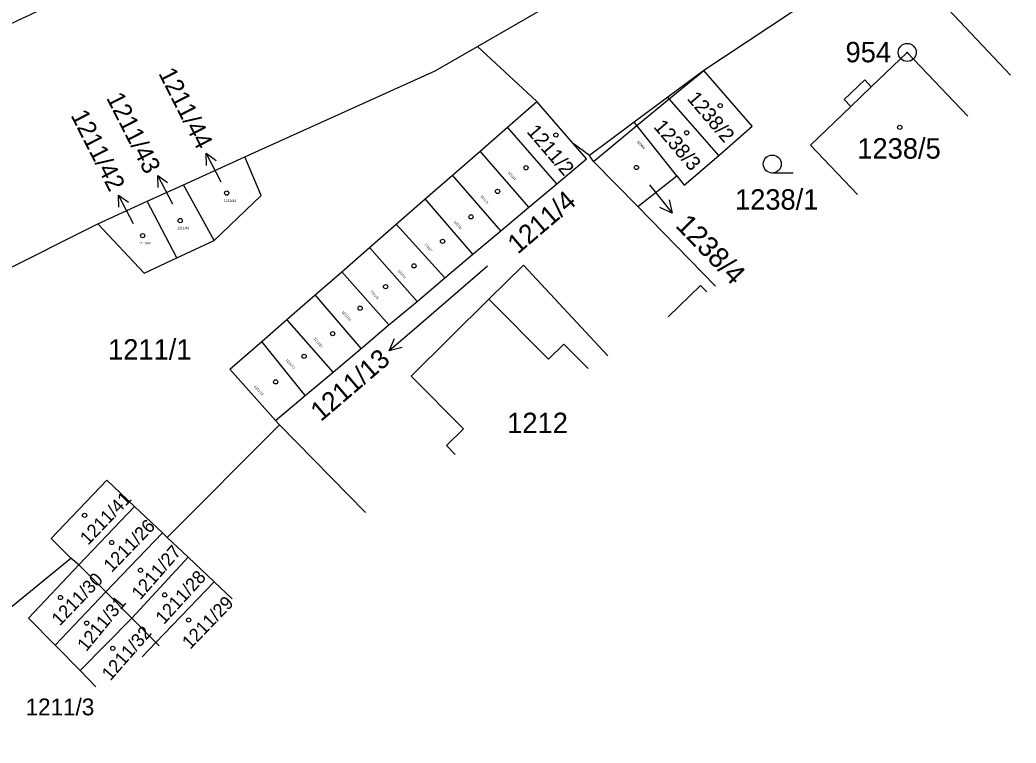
# Model space of a CAD drawing. Extents: x -825057 to -819383, y -1071633 to -1067888.
# Drawn here: x -820150.4 to -820067.4, y -1069566.8 to -1069506.6 of the extents above; entities that cross this region are included whole.
import ezdxf

# ---------------------------------------------------------------- set-up
doc = ezdxf.new("R2010")
doc.units = 0
for name, color, linetype in [('Vrstva 1', 7, 'Continuous'), ('Vrstva 10', 7, 'Continuous'), ('Vrstva 16', 7, 'Continuous'), ('Vrstva 17', 7, 'Continuous'), ('Vrstva 18', 7, 'Continuous'), ('Vrstva 19', 7, 'Continuous'), ('Vrstva 24', 7, 'Continuous'), ('Vrstva 25', 7, 'Continuous'), ('Vrstva 4', 7, 'Continuous')]:
    doc.layers.add(name, color=color, linetype=linetype)

msp = doc.modelspace()

# ---------------------------------------------------------------- linework, layer by layer
at = {"layer": 'Vrstva 1'}
for p, q in [((-820112.25, -1069508.76), (-820085.07, -1069493.07)), ((-820077.91, -1069500.52), (-820093.39, -1069510.76)), ((-820077.91, -1069500.52), (-820067.83, -1069511.15)), ((-820115.78, -1069510.8), (-820112.25, -1069508.76)), ((-820107.3, -1069513.36), (-820112.25, -1069508.76)), ((-820076.45, -1069509.27), (-820079.44, -1069512.13)), ((-820071.39, -1069514.58), (-820076.45, -1069509.27)), ((-820131.65, -1069517.97), (-820115.78, -1069510.8)), ((-820093.39, -1069510.76), (-820096.39, -1069512.99)), ((-820089.36, -1069515.42), (-820093.39, -1069510.76)), ((-820079.99, -1069511.56), (-820081.69, -1069513.18)), ((-820079.44, -1069512.13), (-820079.99, -1069511.56)), ((-820109.74, -1069515.49), (-820107.3, -1069513.36)), ((-820104.28, -1069516.84), (-820107.3, -1069513.36)), ((-820096.39, -1069512.99), (-820099.19, -1069515.08)), ((-820096.27, -1069513.13), (-820096.39, -1069512.99)), ((-820092.15, -1069517.84), (-820096.27, -1069513.13)), ((-820081.69, -1069513.18), (-820081.14, -1069513.76)), ((-820081.14, -1069513.76), (-820084.51, -1069516.99)), ((-820099.19, -1069515.08), (-820102.92, -1069517.86)), ((-820098.97, -1069515.36), (-820099.19, -1069515.08)), ((-820112.04, -1069517.49), (-820109.74, -1069515.49)), ((-820105.64, -1069520.2), (-820109.74, -1069515.49)), ((-820095.65, -1069519.53), (-820098.97, -1069515.36)), ((-820092.15, -1069517.84), (-820089.36, -1069515.42)), ((-820114.34, -1069519.49), (-820112.04, -1069517.49)), ((-820107.97, -1069522.16), (-820112.04, -1069517.49)), ((-820102.92, -1069517.86), (-820104.28, -1069516.84)), ((-820103.16, -1069518.12), (-820104.28, -1069516.84)), ((-820084.51, -1069516.99), (-820080.58, -1069521.09)), ((-820136.74, -1069520.29), (-820131.65, -1069517.97)), ((-820130.28, -1069521.17), (-820131.65, -1069517.97)), ((-820105.64, -1069520.2), (-820103.16, -1069518.12)), ((-820102.59, -1069518.34), (-820102.92, -1069517.86)), ((-820098.9, -1069522.11), (-820102.59, -1069518.34)), ((-820095.02, -1069520.33), (-820092.15, -1069517.84)), ((-820116.6, -1069521.46), (-820114.34, -1069519.49)), ((-820110.3, -1069524.12), (-820114.34, -1069519.49)), ((-820098.9, -1069522.11), (-820095.65, -1069519.53)), ((-820095.65, -1069519.53), (-820095.02, -1069520.33)), ((-820139.77, -1069521.66), (-820136.74, -1069520.29)), ((-820134.2, -1069524.92), (-820136.74, -1069520.29)), ((-820107.97, -1069522.16), (-820105.64, -1069520.2)), ((-820143.89, -1069523.54), (-820139.77, -1069521.66)), ((-820137.31, -1069526.37), (-820139.77, -1069521.66)), ((-820134.2, -1069524.92), (-820130.28, -1069521.17)), ((-820119.02, -1069523.57), (-820116.6, -1069521.46)), ((-820112.63, -1069526.08), (-820116.6, -1069521.46)), ((-820110.3, -1069524.12), (-820107.97, -1069522.16)), ((-820092.42, -1069528.74), (-820098.9, -1069522.11)), ((-820153.6, -1069528.41), (-820143.89, -1069523.54)), ((-820143.89, -1069523.54), (-820140.03, -1069527.64)), ((-820121.24, -1069525.51), (-820119.02, -1069523.57)), ((-820114.96, -1069528.04), (-820119.02, -1069523.57)), ((-820112.63, -1069526.08), (-820110.3, -1069524.12)), ((-820137.31, -1069526.37), (-820134.2, -1069524.92)), ((-820123.56, -1069527.53), (-820121.24, -1069525.51)), ((-820117.29, -1069530), (-820121.24, -1069525.51)), ((-820140.03, -1069527.64), (-820137.31, -1069526.37)), ((-820114.96, -1069528.04), (-820112.63, -1069526.08)), ((-820125.78, -1069529.46), (-820123.56, -1069527.53)), ((-820119.63, -1069531.96), (-820123.56, -1069527.53)), ((-820108.42, -1069526.98), (-820111.3, -1069529.82)), ((-820101.4, -1069534.54), (-820108.42, -1069526.98)), ((-820117.29, -1069530), (-820114.96, -1069528.04)), ((-820128.14, -1069531.52), (-820125.78, -1069529.46)), ((-820121.95, -1069533.92), (-820125.78, -1069529.46)), ((-820119.63, -1069531.96), (-820117.29, -1069530)), ((-820111.3, -1069529.82), (-820117.77, -1069536.24)), ((-820130.22, -1069533.33), (-820128.14, -1069531.52)), ((-820124.29, -1069535.88), (-820128.14, -1069531.52)), ((-820121.95, -1069533.92), (-820119.63, -1069531.96)), ((-820132.89, -1069535.65), (-820130.22, -1069533.33)), ((-820126.62, -1069537.84), (-820130.22, -1069533.33)), ((-820124.29, -1069535.88), (-820121.95, -1069533.92)), ((-820129.09, -1069539.92), (-820132.89, -1069535.65)), ((-820126.62, -1069537.84), (-820124.29, -1069535.88)), ((-820117.77, -1069536.24), (-820113.42, -1069540.6)), ((-820129.09, -1069539.92), (-820126.62, -1069537.84)), ((-820128.76, -1069540.28), (-820129.09, -1069539.92)), ((-820128.76, -1069540.28), (-820138.1, -1069549.65)), ((-820121.59, -1069547.59), (-820128.76, -1069540.28)), ((-820113.42, -1069540.6), (-820114.83, -1069542)), ((-820114.83, -1069542), (-820114.11, -1069542.76)), ((-820147.78, -1069549.75), (-820143.13, -1069544.88)), ((-820143.13, -1069544.88), (-820140.82, -1069547.07)), ((-820140.82, -1069547.07), (-820145.48, -1069551.95)), ((-820140.82, -1069547.07), (-820138.49, -1069549.27)), ((-820146.13, -1069551.39), (-820147.78, -1069549.75)), ((-820138.49, -1069549.27), (-820143.23, -1069554.19)), ((-820138.49, -1069549.27), (-820138.1, -1069549.65)), ((-820138.1, -1069549.65), (-820136.36, -1069551.29)), ((-820165.04, -1069566.78), (-820146.13, -1069551.39)), ((-820145.48, -1069551.95), (-820146.13, -1069551.39)), ((-820136.36, -1069551.29), (-820141.05, -1069556.39)), ((-820136.36, -1069551.29), (-820134.2, -1069553.34)), ((-820145.48, -1069551.95), (-820149.65, -1069556.39)), ((-820143.23, -1069554.19), (-820145.48, -1069551.95)), ((-820134.2, -1069553.34), (-820139.05, -1069558.4)), ((-820134.2, -1069553.34), (-820132.7, -1069554.76)), ((-820143.23, -1069554.19), (-820147.44, -1069558.64)), ((-820141.05, -1069556.39), (-820143.23, -1069554.19)), ((-820149.65, -1069556.39), (-820147.44, -1069558.64)), ((-820141.05, -1069556.39), (-820145.36, -1069560.75)), ((-820139.05, -1069558.4), (-820141.05, -1069556.39)), ((-820147.44, -1069558.64), (-820145.36, -1069560.75)), ((-820139.05, -1069558.4), (-820140.19, -1069559.6)), ((-820138.77, -1069558.68), (-820139.05, -1069558.4)), ((-820145.36, -1069560.75), (-820144.04, -1069562.09))]:
    msp.add_line(p, q, dxfattribs=at)
at = {"layer": 'Vrstva 10'}
for points in [[(-819936.83, -1069349.47), (-819975.71, -1069383.16), (-819999.35, -1069402.16), (-820038.47, -1069432.26), (-820078.04, -1069460.09), (-820109.89, -1069479.65), (-820134.7, -1069493.27), (-820163.02, -1069506.83), (-820195.64, -1069520.53), (-820237.28, -1069534.88), (-820272.75, -1069545.33)], [(-820271.07, -1069550.51), (-820235.31, -1069539.9), (-820193.69, -1069525.37), (-820161.56, -1069511.74), (-820132.38, -1069497.54), (-820107.7, -1069483.92), (-820075.84, -1069464.22), (-820035.7, -1069436.13), (-819996.53, -1069406.13), (-819972.84, -1069386.82), (-819933.47, -1069352.83)]]:
    msp.add_spline(points, degree=3, dxfattribs=at)
at = {"layer": 'Vrstva 16'}
for p, q in [((-820133.6, -1069520.06), (-820134.85, -1069517.667)), ((-820137.64, -1069521.9), (-820138.89, -1069519.507)), ((-820097.91, -1069520.3), (-820096.045, -1069522.65)), ((-820140.9, -1069523.54), (-820142.15, -1069521.147)), ((-820111.43, -1069527.07), (-820117.34, -1069532.16)), ((-820117.34, -1069532.16), (-820119.612, -1069534.119))]:
    msp.add_line(p, q, dxfattribs=at)
for points in [[(-820134.832, -1069518.673), (-820134.85, -1069517.667), (-820134.034, -1069518.256)], [(-820138.872, -1069520.513), (-820138.89, -1069519.507), (-820138.074, -1069520.096)], [(-820142.132, -1069522.153), (-820142.15, -1069521.147), (-820141.334, -1069521.736)], [(-820096.275, -1069521.556), (-820096.045, -1069522.65), (-820097.058, -1069522.177)], [(-820118.529, -1069533.844), (-820119.612, -1069534.119), (-820119.181, -1069533.087)]]:
    msp.add_lwpolyline(points, dxfattribs=at)
at = {"layer": 'Vrstva 24'}
for radius in [0.75, 0.0327]:
    msp.add_circle((-820076.45, -1069509.27), radius, dxfattribs=at)
at = {"layer": 'Vrstva 25'}
msp.add_line((-820085.94, -1069519.31), (-820087.69, -1069519.31), dxfattribs=at)
for centre, radius in [((-820092.03, -1069513.7), 0.175), ((-820094.82, -1069515.96), 0.175), ((-820077.07, -1069515.51), 0.175), ((-820105.72, -1069516.14), 0.175), ((-820087.69, -1069518.56), 0.75), ((-820108.21, -1069518.87), 0.175), ((-820099.01, -1069518.85), 0.175), ((-820133.15, -1069520.98), 0.175), ((-820110.58, -1069520.84), 0.175), ((-820137.02, -1069523.27), 0.175), ((-820112.79, -1069522.96), 0.175), ((-820140.15, -1069524.53), 0.175), ((-820115.16, -1069525), 0.175), ((-820117.54, -1069527.04), 0.175), ((-820119.91, -1069528.77), 0.175), ((-820122.03, -1069530.57), 0.175), ((-820124.32, -1069532.69), 0.175), ((-820126.7, -1069534.58), 0.175), ((-820129.07, -1069536.7), 0.175), ((-820144.99, -1069547.82), 0.175), ((-820142.73, -1069550.08), 0.175), ((-820140.33, -1069552.39), 0.175), ((-820147, -1069554.66), 0.175), ((-820138.32, -1069554.44), 0.175), ((-820136.32, -1069556.53), 0.175), ((-820144.82, -1069556.79), 0.175), ((-820142.64, -1069558.89), 0.175)]:
    msp.add_circle(centre, radius, dxfattribs=at)
at = {"layer": 'Vrstva 4'}
for p, q in [((-820096.27, -1069513.13), (-820093.39, -1069510.76)), ((-820081.14, -1069513.76), (-820079.44, -1069512.13)), ((-820098.97, -1069515.36), (-820096.27, -1069513.13)), ((-820102.59, -1069518.34), (-820098.97, -1069515.36)), ((-820096.37, -1069531.29), (-820093.67, -1069528.67)), ((-820093.67, -1069528.67), (-820093.15, -1069529.21)), ((-820111.3, -1069529.82), (-820106.34, -1069534.81)), ((-820106.34, -1069534.81), (-820105.07, -1069533.55)), ((-820105.07, -1069533.55), (-820103.03, -1069535.59))]:
    msp.add_line(p, q, dxfattribs=at)

# ---------------------------------------------------------------- texts
at = {"layer": 'Vrstva 16'}
for s, height, rotation, p in [('1211/44', 1.5, 297, (-820138.867, -1069510.997)), ('1211/43', 1.5, 297, (-820143.211, -1069513.048)), ('1211/42', 1.5, 297, (-820146.178, -1069514.496)), ('1211/4', 1.6, 40.5, (-820108.889, -1069526.118)), ('1238/4', 1.7, 314.1, (-820095.833, -1069523.749)), ('1211/13', 1.6, 40.5, (-820125.303, -1069540.061))]:
    msp.add_text(s, height=height, rotation=rotation, dxfattribs=at).set_placement(p)
at = {"layer": 'Vrstva 17'}
msp.add_text('954', height=1.7, dxfattribs=at).set_placement((-820081.59, -1069510.09))
at = {"layer": 'Vrstva 18'}
for s, height, p in [('1238/1', 1.7, (-820090.798, -1069522.36)), ('1211/1', 1.7, (-820143.034, -1069534.85)), ('1211/3', 1.4, (-820149.906, -1069564.47))]:
    msp.add_text(s, height=height, dxfattribs=at).set_placement(p)
at = {"layer": 'Vrstva 19'}
for s, height, rotation, p in [('1238/2', 1.2, 310.5, (-820094.845, -1069513.144)), ('1238/3', 1.2, 310.5, (-820097.639, -1069515.489)), ('1211/2', 1.2, 310.5, (-820108.205, -1069515.898)), ('1238/4', 0.2, 313.2, (-820098.973, -1069516.742)), ('1211/4', 0.2, 310.5, (-820109.729, -1069519.292)), ('1211/5', 0.2, 310.5, (-820112.021, -1069521.259)), ('1211/6', 0.2, 310.5, (-820114.229, -1069523.382)), ('1211/7', 0.2, 310.5, (-820116.686, -1069525.265)), ('1211/8', 0.2, 311.4, (-820118.893, -1069527.474)), ('1211/9', 0.2, 310.5, (-820121.179, -1069529.182)), ('1211/10', 0.2, 311.4, (-820123.572, -1069530.892)), ('1211/11', 0.2, 310.5, (-820125.918, -1069533.113)), ('1211/12', 0.2, 311.4, (-820128.244, -1069534.909)), ('1211/13', 0.2, 311.4, (-820130.874, -1069537.099)), ('1211/41', 1.1, 46.1889, (-820144.695, -1069550.352)), ('1211/26', 1.1, 45.9153, (-820142.734, -1069552.624)), ('1211/27', 1.1, 48.9519, (-820140.352, -1069554.914)), ('1211/28', 1.1, 47.6946, (-820138.379, -1069556.958)), ('1211/30', 1.1, 46.0449, (-820147.063, -1069557.079)), ('1211/31', 1.1, 50.4927, (-820144.851, -1069559.221)), ('1211/29', 1.1, 46.0422, (-820136.191, -1069559.026)), ('1211/32', 1.1, 48.8079, (-820142.833, -1069561.644))]:
    msp.add_text(s, height=height, rotation=rotation, dxfattribs=at).set_placement(p)
for s, height, p in [('1238/5', 1.7, (-820080.607, -1069518.11)), ('1211/44', 0.2, (-820133.376, -1069521.71)), ('1211/43', 0.2, (-820137.274, -1069523.99)), ('1211/42', 0.2, (-820140.482, -1069525.26)), ('1212', 1.7, (-820109.778, -1069540.97))]:
    msp.add_text(s, height=height, dxfattribs=at).set_placement(p)

doc.saveas('drawing.dxf')
